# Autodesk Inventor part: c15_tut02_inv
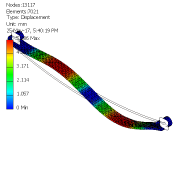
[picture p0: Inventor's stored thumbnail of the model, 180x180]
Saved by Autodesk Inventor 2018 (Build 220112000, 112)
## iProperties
Created: 2017-05
Part Number: c15_tut02_inv
Material: Steel, Mild
Document SubType Name: Modeling
Designer: CADCIM 00
Mass: 5.6491 g
Surface Area: 16.9114 cm^2
Volume: 0.71963 cm^3
Density: 7.85 g/cm^3
Appearance: Semi-Polished
Author: CADCIM 00
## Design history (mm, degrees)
sketch "Sketch1"
  geometry: L1 (0, 0)-(0, 18.068); L2 (48.5, 8.9)-(47.5, 8.9); L3 (-48.5, 8.9)-(-47.5, 8.9); A1 r 200 centre (0, 201) between (-50.378, 7.449) and (50.378, 7.449); A2 r 201 centre (0, 201) between (-50.63, 6.481) and (50.63, 6.481); A3 r 1.5 centre (50, 8.9) between (50.378, 7.449) and (48.5, 8.9); A4 r 2.5 centre (50, 8.9) between (50.63, 6.481) and (47.5, 8.9); A5 r 1.5 centre (-50, 8.9) between (-48.5, 8.9) and (-50.378, 7.449); A6 r 2.5 centre (-50, 8.9) between (-47.5, 8.9) and (-50.63, 6.481); 5 further points
  constraints: 13 point on circle, 6 centre point, 6 end point, 6 symmetric about line, 5 horizontal alignment, 3 coincident, 2 tangent, 1 horizontal, 1 midpoint, 1 vertical, 2 other
  dimensions: "d0" = 200 radius of A1; "d1" = 1 radial gap between concentric circles of A2 A1; "d2" = 2.5 radius of A4; "d3" = 50 distance from line of L1 A3.centre
extrude "Extrusion1" new body sketch "Sketch1" distance "d4" = 6; taper "d5" = 0 deg
body "Solid1"
